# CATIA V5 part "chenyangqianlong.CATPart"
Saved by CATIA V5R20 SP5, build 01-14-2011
Part number: Part1
Bounding box of the stored display mesh (mm): x -156.065 to 110, y -40 to 40, z -36.055 to 54.002
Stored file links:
  E:\180131128 陈阳黔龙\chenyangqianlong.CATPart
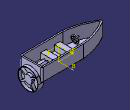
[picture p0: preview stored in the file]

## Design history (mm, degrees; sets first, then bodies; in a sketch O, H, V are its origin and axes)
Body1 (main body)
  Sketch1 on xy-plane, origin (0, 0, 0), H (1, 0, 0), V (0, 1, 0)
    point P1 (-50, 40)
    line L1 (-50, 40) -> (100, 40)
    line L2 (100, 40) -> (100, -40)
    line L3 (100, -40) -> (-50, -40)
    point P4 (-50, -40)
    spline S1 through (-50, 40) (-100, 30) (-160, 0)
    spline S2 through (-160, 0) (-100, -30) (-50, -40)
    point P5 (-50, 40)
    point P6 (-160, 0)
    point P7 (-160, 0)
    point P8 (-50, -40)
    horizontal: L1 H, L3 H
    vertical: L2 V
    coincidence: P5 P1, P6 P7, P8 P4
  Pad1: profile Sketch1, direction (0, 0, 1), length 50
  Sketch2 on end face of Pad1, origin (0, 0, 50), H (1, 0, 0), V (0, 1, 0)
  Fillet1: radius 5, on edge [face of Pad1 from Sketch1.S1 | face of Pad1 from Sketch1.L1]; edge [face of Pad1 from Sketch1.L1 | face of Pad1 from Sketch1.L2]; edge [face of Pad1 from Sketch1.L2 | face of Pad1 from Sketch1.L3]; edge [face of Pad1 from Sketch1.L3 | face of Pad1 from Sketch1.S2]; edge [face of Pad1 from Sketch1.S2 | face of Pad1 from Sketch1.S1]
  Fillet2: radius 5, on edge [start face of Pad1 | face of Pad1 from Sketch1.L3]
  Shell1: ExtOffset 0, Face end face of Pad1, IntOffset 5
  Plane1: type Offset, RefPlane yz-plane, Offset 100
  Sketch3 on Plane1, origin (100, 0, 0), H (0, 1, 0), V (0, 0, 1)
    circle A1 centre (0, 0) radius 36.0555
  Pad2: profile Sketch3, direction (1, 0, 0), length 10, mirrored extent
  Sketch4 on zx-plane, origin (0, 0, 0), H (-1, 0, 0), V (0, 0, 1)
    construction line L1 (-90, 20) -> (-50, 20)
    line L2 (-90, 30) -> (-50, 30)
    line L3 (-50, 10) -> (-90, 10)
    arc A1 centre (-50, 20) radius 10 from (-50, 30) to (-50, 10) cw
    arc A2 centre (-90, 20) radius 10 from (-90, 10) to (-90, 30) cw
    distance L1 L2 = 10
    horizontal: L1 H
    tangency: A1 L2, A2 L2, A1 L3, A2 L3
  Pad3: profile Sketch4, direction (0, 1, 0), length 10, mirrored extent
  Fillet3: radius 5, on edge [start face of Pad3 | face of Pad3 from Sketch4.L2]; edge [face of Pad3 from Sketch4.L2 | end face of Pad3]
  Sketch5 on xy-plane, origin (0, 0, 0), H (1, 0, 0), V (0, 1, 0)
    line L1 (10, 40) -> (30, 40)
    line L2 (30, 40) -> (30, -40)
    line L3 (30, -40) -> (10, -40)
    line L4 (10, -40) -> (10, 40)
    line L5 (-40, 40) -> (-20, 40)
    line L6 (-20, 40) -> (-20, -40)
    line L7 (-20, -40) -> (-40, -40)
    line L8 (-40, -40) -> (-40, 40)
    horizontal: L1 H, L3 H, L5 H, L7 H
    vertical: L2 V, L4 V, L6 V, L8 V
  Pad4: profile Sketch5, direction (0, 0, 1), length 25
  Fillet4: radius 5, on edge [face of Pad4 | face of Pad4] (x4)
  Sketch6 on end face of Pad2, origin (110, 0, 0), H (0, 1, 0), V (0, 0, 1)
    point P1 (0, 0)
  Hole1: placed by Sketch6, at (110, 0, 0) direction (-1, 0, 0), diameter 69, depth 10
  Sketch7 on Plane1, origin (100, 0, 0), H (0, 1, 0), V (0, 0, 1)
    spline S1 through (0, 0) (10, 10) (30, 20) (20, 10) (0, 0)
    point P1 (0, 0)
    point P2 (0, 0)
    coincidence: P1 O, P2 O
  Pad5: profile Sketch7, direction (1, 0, 0), length 10
  Sketch8 on face of Hole1, origin (100, 0, 0), H (0, 1, 0), V (0, 0, 1)
    spline S1 through (0, 0) (-10, -10) (-30, -20) (-20, -10) (0, 0)
    point P1 (0, 0)
    point P2 (0, 0)
    coincidence: P1 O, P2 O
  Pad6: profile Sketch8, direction (1, 0, 0), length 10
  Sketch9 on face of Hole1, origin (100, 0, 0), H (0, 1, 0), V (0, 0, 1)
    spline S1 through (0, 0) (10, -10) (20, -30) (10, -20) (0, 0)
    point P1 (0, 0)
    point P2 (0, 0)
    coincidence: P1 O, P2 O
  Pad7: profile Sketch9, direction (1, 0, 0), length 10
  Sketch10 on Plane1, origin (100, 0, 0), H (0, 1, 0), V (0, 0, 1)
    spline S1 through (0, 0) (-10, 10) (-30, 20) (-20, 10) (0, 0)
    point P1 (0, 0)
    point P2 (0, 0)
    coincidence: P1 O, P2 O
  Pad8: profile Sketch10, direction (1, 0, 0), length 10
  Pocket1: profile face of Pad8, direction along face of Pad8, length 10
  Sketch11 on zx-plane, origin (0, 0, 0), H (-1, 0, 0), V (0, 0, 1)
  Sketch12 on zx-plane, origin (0, 0, 0), H (-1, 0, 0), V (0, 0, 1)
    line L1 (-80, 0) -> (-80, -20)
    point P1 (-80, 0)
    point P2 (-80, -20)
    spline S1 through (-80, -20) (-70, -10) (-70, 0)
    line L2 (-70, 0) -> (-80, 0)
    point P3 (-70, 0)
    point P4 (-80, -20)
    point P5 (-70, 0)
    coincidence: P1 H, P4 P2, P5 P3
    vertical: L1 V
    horizontal: L2 H
  Pad9: profile Sketch12, direction (0, 1, 0), length 5, mirrored extent
  Sketch13 on Plane1, origin (100, 0, 0), H (0, 1, 0), V (0, 0, 1)
    circle A1 centre (0, 0) radius 14.1421
  Pad10: profile Sketch13, direction (1, 0, 0), length 10
  Sketch14 on yz-plane, origin (0, 0, 0), H (0, 1, 0), V (0, 0, 1)
  Sketch15 on yz-plane, origin (0, 0, 0), H (0, 1, 0), V (0, 0, 1)
  Plane2: type Offset, RefPlane yz-plane, Offset -60
  Sketch16 on Plane2, origin (-60, 0, 0), H (0, 1, 0), V (0, 0, 1)
    circle A1 centre (0, 40) radius 14.1421
  Pad11: profile Sketch16, direction (1, 0, 0), length 3, mirrored extent
  Sketch17 on Plane2, origin (-60, 0, 0), H (0, 1, 0), V (0, 0, 1)
    circle A1 centre (0, 40) radius 2.5
    radius A1 = 2.5
  Pad12: profile Sketch17, direction (-1, 0, 0), length 10
  Sketch18 on xy-plane, origin (0, 0, 0), H (1, 0, 0), V (0, 1, 0)
    circle A1 centre (-70, 0) radius 3
    point P1 (-70, 0)
    radius A1 = 3
    coincidence: P1 H
  Pad13: profile Sketch18, direction (0, 0, 1), length 43
  Sketch19 on Plane2, origin (-60, 0, 0), H (0, 1, 0), V (0, 0, 1)
    circle A1 centre (0, 40) radius 10
  Pocket2: profile Sketch19, direction (-1, 0, 0), length 3, mirrored extent
  Fillet5: on edge [face of Pad11 from Sketch16.A1 | end face of Pad11]
  Fillet6: on edge [start face of Pad11 | face of Pad11 from Sketch16.A1]
  Sketch20 on Plane2, origin (-60, 0, 0), H (0, 1, 0), V (0, 0, 1)
    line L1 (-10, 42.5) -> (10, 42.5)
    line L2 (10, 42.5) -> (10, 37.5)
    line L3 (10, 37.5) -> (-10, 37.5)
    line L4 (-10, 37.5) -> (-10, 42.5)
    length L2 = 5
    horizontal: L1 H, L3 H
    vertical: L2 V, L4 V
  Pad14: profile Sketch20, direction (1, 0, 0), length 3, mirrored extent
  Fillet7: on edge [face of Pad14 from Sketch20.L1 | face of Pad14]
  Fillet8: on edge [face of Pad14 from Sketch20.L3 | face of Pad14]
  Sketch21 on Plane2, origin (-60, 0, 0), H (0, 1, 0), V (0, 0, 1)
    line L1 (-2.5, 50) -> (2.5, 50)
    line L2 (2.5, 50) -> (2.5, 30)
    line L3 (2.5, 30) -> (-2.5, 30)
    line L4 (-2.5, 30) -> (-2.5, 50)
    length L1 = 5
    horizontal: L1 H, L3 H
    vertical: L2 V, L4 V
  Pad15: profile Sketch21, direction (1, 0, 0), length 3, mirrored extent
  Fillet9: on edge [face of Pad15 from Sketch21.L2 | face of Pad15]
